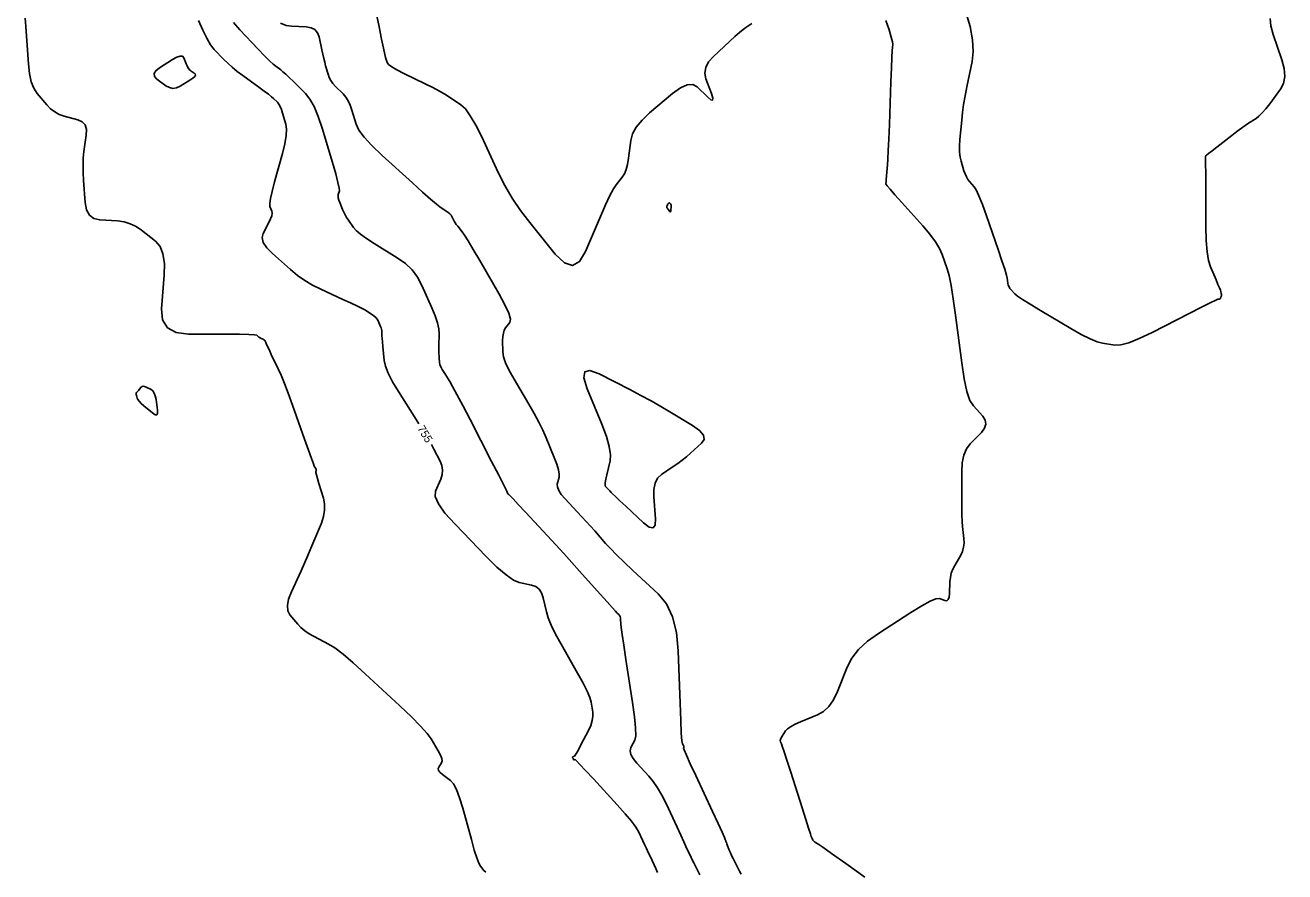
# Model space of a CAD drawing. Extents: x 2082232 to 2083549, y 592624 to 593832.
# Drawn here: x 2082685.8 to 2082796, y 593100.6 to 593174.7 of the extents above; entities that cross this region are included whole.
import ezdxf

# ---------------------------------------------------------------- set-up
doc = ezdxf.new("R2010")
doc.units = 0
doc.layers.add('DT_X_Contour_Major', color=7, linetype='Continuous')
doc.layers.add('DT_X_Contour_Minor', color=7, linetype='Continuous')

msp = doc.modelspace()

# ---------------------------------------------------------------- linework, layer by layer
at = {"layer": 'DT_X_Contour_Major'}
for points in [[(2082700.93, 593175.1), (2082701.29, 593174.24), (2082701.64, 593173.54), (2082701.98, 593172.98), (2082702.3, 593172.57), (2082703.14, 593171.69), (2082703.48, 593171.36), (2082703.87, 593171.01), (2082704.31, 593170.65), (2082704.8, 593170.28), (2082706.19, 593169.27), (2082706.66, 593168.92), (2082707.04, 593168.64), (2082707.31, 593168.42), (2082707.48, 593168.26), (2082707.82, 593167.94), (2082707.94, 593167.78), (2082708.06, 593167.57), (2082708.17, 593167.3), (2082708.28, 593166.98), (2082708.56, 593166.02), (2082708.62, 593165.6), (2082708.59, 593165.03), (2082708.47, 593164.31), (2082708.26, 593163.46), (2082707.56, 593160.98), (2082707.35, 593160.15), (2082707.21, 593159.52), (2082707.15, 593159.08), (2082707.17, 593158.83), (2082707.33, 593158.43), (2082707.36, 593158.25), (2082707.33, 593158.02), (2082707.23, 593157.75), (2082707.08, 593157.42), (2082706.58, 593156.47), (2082706.49, 593156.1), (2082706.59, 593155.68), (2082706.89, 593155.22), (2082707.38, 593154.71), (2082708.96, 593153.3), (2082709.57, 593152.8), (2082710.21, 593152.34), (2082710.89, 593151.94), (2082711.61, 593151.58), (2082713.56, 593150.7), (2082714.23, 593150.4), (2082714.77, 593150.14), (2082715.18, 593149.93), (2082715.47, 593149.77), (2082716.05, 593149.41), (2082716.25, 593149.27), (2082716.42, 593149.12), (2082716.54, 593148.97), (2082716.63, 593148.81), (2082716.82, 593148.37), (2082716.89, 593148.22), (2082716.93, 593148.09), (2082716.96, 593147.97), (2082716.96, 593147.88), (2082716.96, 593147.64), (2082716.96, 593147.51), (2082716.98, 593147.29), (2082717.01, 593146.97), (2082717.04, 593146.57), (2082717.16, 593145.36), (2082717.27, 593144.86), (2082717.52, 593144.23), (2082717.89, 593143.49), (2082718.41, 593142.64), (2082719.95, 593140.2), (2082720.2, 593139.81)], [(2082721.29, 593138.01), (2082721.52, 593137.59), (2082722.05, 593136.55), (2082722.2, 593136.16), (2082722.26, 593135.77), (2082722.23, 593135.37), (2082722.11, 593134.98), (2082721.65, 593133.93), (2082721.63, 593133.45), (2082721.91, 593132.81), (2082722.48, 593132), (2082723.36, 593131.03), (2082726.09, 593128.21), (2082727.03, 593127.28), (2082727.83, 593126.59), (2082728.47, 593126.14), (2082728.96, 593125.93), (2082730.05, 593125.7), (2082730.43, 593125.57), (2082730.72, 593125.34), (2082730.94, 593125.02), (2082731.08, 593124.6), (2082731.36, 593123.36), (2082731.51, 593122.83), (2082731.78, 593122.18), (2082732.16, 593121.42), (2082732.64, 593120.53), (2082734.09, 593118), (2082734.57, 593117.13), (2082734.93, 593116.42), (2082735.17, 593115.86), (2082735.28, 593115.45), (2082735.42, 593114.58), (2082735.43, 593114.23), (2082735.37, 593113.85), (2082735.24, 593113.43), (2082735.03, 593112.97), (2082734.37, 593111.71), (2082734.15, 593111.3), (2082733.98, 593111), (2082733.86, 593110.81), (2082733.8, 593110.73), (2082733.7, 593110.69), (2082733.67, 593110.67), (2082733.65, 593110.66), (2082733.64, 593110.64), (2082733.65, 593110.63), (2082733.67, 593110.6), (2082733.68, 593110.59), (2082733.69, 593110.57), (2082733.7, 593110.55), (2082733.7, 593110.52), (2082733.72, 593110.46), (2082733.72, 593110.44), (2082733.74, 593110.42), (2082733.76, 593110.42), (2082733.78, 593110.42), (2082733.86, 593110.43), (2082733.98, 593110.33), (2082734.29, 593110.01), (2082734.79, 593109.48), (2082735.48, 593108.74), (2082737.56, 593106.47), (2082738.26, 593105.69), (2082738.8, 593105.04), (2082739.19, 593104.52), (2082739.41, 593104.14), (2082739.8, 593103.31), (2082739.95, 593102.99), (2082740.11, 593102.65), (2082740.27, 593102.29), (2082740.45, 593101.92), (2082740.92, 593100.89), (2082741.08, 593100.55)]]:
    msp.add_lwpolyline(points, dxfattribs=at)
at = {"layer": 'DT_X_Contour_Minor'}
for points in [[(2082716.04, 593177.72), (2082716.71, 593174.54), (2082716.93, 593173.48), (2082717.11, 593172.67), (2082717.23, 593172.13), (2082717.29, 593171.85), (2082717.41, 593171.43), (2082717.53, 593171.26), (2082717.82, 593171.04), (2082718.28, 593170.77), (2082718.89, 593170.46), (2082720.75, 593169.56), (2082721.41, 593169.24), (2082721.99, 593168.93), (2082722.48, 593168.65), (2082722.89, 593168.39), (2082723.88, 593167.72), (2082724.27, 593167.36), (2082724.7, 593166.77), (2082725.18, 593165.95), (2082725.7, 593164.91), (2082727.14, 593161.81), (2082727.72, 593160.67), (2082728.37, 593159.56), (2082729.09, 593158.47), (2082729.9, 593157.42), (2082732.13, 593154.66), (2082732.93, 593153.89), (2082733.64, 593153.67), (2082734.26, 593154), (2082734.79, 593154.88), (2082736.09, 593157.94), (2082736.54, 593158.98), (2082736.92, 593159.79), (2082737.22, 593160.38), (2082737.46, 593160.73), (2082737.99, 593161.39), (2082738.18, 593161.68), (2082738.33, 593162.05), (2082738.45, 593162.5), (2082738.54, 593163.04), (2082738.74, 593164.59), (2082738.9, 593165.18), (2082739.22, 593165.78), (2082739.72, 593166.39), (2082740.38, 593167.01), (2082742.38, 593168.7), (2082743.08, 593169.21), (2082743.68, 593169.48), (2082744.17, 593169.5), (2082744.56, 593169.29), (2082745.48, 593168.39), (2082745.75, 593168.15), (2082745.9, 593168.13), (2082745.91, 593168.31), (2082745.79, 593168.7), (2082745.3, 593170), (2082745.21, 593170.5), (2082745.29, 593170.99), (2082745.54, 593171.47), (2082745.98, 593171.96), (2082747.37, 593173.26), (2082747.85, 593173.71), (2082748.25, 593174.06), (2082748.57, 593174.32), (2082748.81, 593174.49), (2082749.34, 593174.83)], [(2082726.05, 593100.59), (2082725.87, 593100.74), (2082725.58, 593101.11), (2082725.45, 593101.36), (2082725.27, 593101.83), (2082725.05, 593102.52), (2082724.79, 593103.44), (2082724.04, 593106.17), (2082723.76, 593107.09), (2082723.49, 593107.81), (2082723.22, 593108.31), (2082722.96, 593108.61), (2082722.27, 593109.12), (2082722.05, 593109.31), (2082721.93, 593109.48), (2082721.89, 593109.64), (2082721.94, 593109.78), (2082722.19, 593110.14), (2082722.24, 593110.31), (2082722.21, 593110.54), (2082722.1, 593110.83), (2082721.9, 593111.19), (2082721.27, 593112.24), (2082720.92, 593112.71), (2082720.34, 593113.35), (2082719.54, 593114.16), (2082718.52, 593115.13), (2082715.5, 593117.95), (2082714.45, 593118.9), (2082713.57, 593119.65), (2082712.85, 593120.2), (2082712.3, 593120.54), (2082711.05, 593121.19), (2082710.61, 593121.44), (2082710.22, 593121.71), (2082709.88, 593121.99), (2082709.6, 593122.29), (2082708.92, 593123.11), (2082708.74, 593123.46), (2082708.7, 593123.91), (2082708.8, 593124.46), (2082709.05, 593125.11), (2082709.89, 593126.95), (2082710.2, 593127.63), (2082710.49, 593128.29), (2082710.76, 593128.93), (2082711.02, 593129.53), (2082711.67, 593131.13), (2082711.86, 593131.71), (2082711.95, 593132.27), (2082711.95, 593132.8), (2082711.85, 593133.3), (2082711.45, 593134.59), (2082711.32, 593135.02), (2082711.23, 593135.34), (2082711.18, 593135.54), (2082711.18, 593135.63), (2082711.22, 593135.71), (2082711.22, 593135.75), (2082711.22, 593135.79), (2082711.2, 593135.85), (2082711.16, 593135.92), (2082711.05, 593136.11), (2082710.97, 593136.32), (2082710.79, 593136.78), (2082710.53, 593137.5), (2082710.18, 593138.48), (2082709.14, 593141.45), (2082708.77, 593142.48), (2082708.44, 593143.35), (2082708.15, 593144.07), (2082707.9, 593144.62), (2082707.29, 593145.89), (2082707.09, 593146.31), (2082706.94, 593146.63), (2082706.85, 593146.83), (2082706.8, 593146.93), (2082706.74, 593147.05), (2082706.72, 593147.1), (2082706.68, 593147.14), (2082706.63, 593147.17), (2082706.57, 593147.21), (2082706.39, 593147.29), (2082706.32, 593147.32), (2082706.26, 593147.36), (2082706.2, 593147.4), (2082706.15, 593147.44), (2082706.01, 593147.56), (2082705.81, 593147.6), (2082705.31, 593147.63), (2082704.5, 593147.65), (2082703.4, 593147.65), (2082700.04, 593147.65), (2082698.95, 593147.79), (2082698.2, 593148.21), (2082697.78, 593148.9), (2082697.69, 593149.87), (2082697.91, 593152.83), (2082697.93, 593153.84), (2082697.81, 593154.67), (2082697.55, 593155.32), (2082697.16, 593155.78), (2082695.93, 593156.75), (2082695.45, 593157.08), (2082694.94, 593157.32), (2082694.4, 593157.48), (2082693.84, 593157.56), (2082692.28, 593157.65), (2082691.77, 593157.78), (2082691.38, 593158.07), (2082691.13, 593158.53), (2082691.01, 593159.17), (2082690.86, 593161.09), (2082690.82, 593161.79), (2082690.82, 593162.45), (2082690.84, 593163.06), (2082690.9, 593163.63), (2082691.1, 593165.08), (2082691.11, 593165.57), (2082690.99, 593165.96), (2082690.74, 593166.23), (2082690.36, 593166.41), (2082689.17, 593166.73), (2082688.74, 593166.88), (2082688.34, 593167.1), (2082687.98, 593167.38), (2082687.64, 593167.72), (2082686.79, 593168.72), (2082686.51, 593169.17), (2082686.29, 593169.74), (2082686.13, 593170.45), (2082686.04, 593171.3), (2082685.88, 593173.73), (2082685.82, 593174.58), (2082685.76, 593175.29)], [(2082794.69, 593175.26), (2082794.73, 593174.62), (2082794.94, 593173.86), (2082795.7, 593171.67), (2082795.91, 593170.89), (2082795.96, 593170.2), (2082795.85, 593169.59), (2082795.57, 593169.08), (2082794.64, 593167.81), (2082794.3, 593167.37), (2082793.98, 593167.01), (2082793.7, 593166.73), (2082793.44, 593166.53), (2082792.77, 593166.11), (2082792.5, 593165.92), (2082792.16, 593165.68), (2082791.76, 593165.38), (2082791.31, 593165.03), (2082790.02, 593164.03), (2082789.6, 593163.69), (2082789.29, 593163.46), (2082789.11, 593163.31), (2082789.05, 593163.26), (2082789.04, 593163.26), (2082789.04, 593163.26), (2082789.04, 593163.25), (2082789.04, 593163.25), (2082789.04, 593163.25), (2082789.04, 593163.25), (2082789.04, 593163.25), (2082789.04, 593163.25), (2082789.04, 593163.25), (2082789.03, 593163.24), (2082789.03, 593163.23), (2082789.03, 593163.07), (2082789.03, 593162.57), (2082789.04, 593161.74), (2082789.04, 593160.59), (2082789.06, 593157.07), (2082789.09, 593155.86), (2082789.17, 593154.87), (2082789.29, 593154.1), (2082789.45, 593153.56), (2082789.95, 593152.4), (2082790.11, 593152.01), (2082790.24, 593151.71), (2082790.32, 593151.51), (2082790.35, 593151.39), (2082790.4, 593151.21), (2082790.41, 593151.14), (2082790.42, 593151.09), (2082790.42, 593151.04), (2082790.41, 593151), (2082790.37, 593150.9), (2082790.36, 593150.86), (2082790.34, 593150.84), (2082790.33, 593150.81), (2082790.32, 593150.8), (2082790.3, 593150.76), (2082790.29, 593150.75), (2082790.27, 593150.74), (2082790.24, 593150.73), (2082790.2, 593150.73), (2082790.1, 593150.72), (2082789.92, 593150.64), (2082789.43, 593150.41), (2082788.66, 593150.02), (2082787.59, 593149.47), (2082784.34, 593147.8), (2082783.22, 593147.27), (2082782.31, 593146.9), (2082781.6, 593146.71), (2082781.09, 593146.68), (2082780.02, 593146.86), (2082779.55, 593146.99), (2082778.92, 593147.25), (2082778.15, 593147.64), (2082777.23, 593148.16), (2082774.58, 593149.73), (2082773.69, 593150.27), (2082773.02, 593150.68), (2082772.57, 593150.99), (2082772.34, 593151.18), (2082772.02, 593151.53), (2082771.91, 593151.66), (2082771.83, 593151.8), (2082771.77, 593151.95), (2082771.73, 593152.11), (2082771.68, 593152.54), (2082771.61, 593152.81), (2082771.46, 593153.33), (2082771.21, 593154.08), (2082770.87, 593155.06), (2082769.85, 593158.01), (2082769.5, 593159), (2082769.2, 593159.75), (2082768.96, 593160.27), (2082768.78, 593160.56), (2082768.38, 593161), (2082768.24, 593161.19), (2082768.11, 593161.41), (2082767.99, 593161.67), (2082767.89, 593161.96), (2082767.63, 593162.79), (2082767.55, 593163.14), (2082767.51, 593163.58), (2082767.5, 593164.09), (2082767.54, 593164.68), (2082767.69, 593166.38), (2082767.76, 593167.04), (2082767.86, 593167.74), (2082767.99, 593168.5), (2082768.14, 593169.3), (2082768.6, 593171.5), (2082768.69, 593172.39), (2082768.63, 593173.41), (2082768.42, 593174.56), (2082768.06, 593175.83)], [(2082703.99, 593174.92), (2082704.54, 593174.29), (2082706.15, 593172.59), (2082706.69, 593172.02), (2082707.13, 593171.58), (2082707.46, 593171.27), (2082707.68, 593171.09), (2082708.11, 593170.77), (2082708.3, 593170.62), (2082708.55, 593170.4), (2082708.86, 593170.11), (2082709.23, 593169.75), (2082710.28, 593168.71), (2082710.67, 593168.23), (2082711.04, 593167.56), (2082711.4, 593166.71), (2082711.74, 593165.68), (2082712.64, 593162.67), (2082712.92, 593161.67), (2082713.12, 593160.93), (2082713.23, 593160.43), (2082713.24, 593160.19), (2082713.15, 593159.87), (2082713.14, 593159.74), (2082713.15, 593159.58), (2082713.2, 593159.39), (2082713.28, 593159.17), (2082713.52, 593158.55), (2082713.63, 593158.32), (2082713.74, 593158.09), (2082713.88, 593157.85), (2082714.03, 593157.62), (2082714.47, 593156.99), (2082714.7, 593156.73), (2082715.09, 593156.41), (2082715.62, 593156.03), (2082716.3, 593155.59), (2082718.31, 593154.34), (2082719.02, 593153.84), (2082719.61, 593153.27), (2082720.09, 593152.63), (2082720.47, 593151.92), (2082721.34, 593149.95), (2082721.62, 593149.25), (2082721.82, 593148.64), (2082721.94, 593148.12), (2082721.97, 593147.68), (2082721.95, 593146.63), (2082721.95, 593146.27), (2082721.95, 593145.97), (2082721.96, 593145.73), (2082721.97, 593145.56), (2082722, 593145.17), (2082722.04, 593145.01), (2082722.12, 593144.81), (2082722.24, 593144.57), (2082722.4, 593144.29), (2082722.9, 593143.51), (2082723.15, 593143.08), (2082723.53, 593142.39), (2082724.04, 593141.42), (2082724.68, 593140.18), (2082726.56, 593136.51), (2082727.18, 593135.31), (2082727.62, 593134.45), (2082727.88, 593133.93), (2082727.96, 593133.75), (2082727.96, 593133.74), (2082727.96, 593133.73), (2082727.96, 593133.72), (2082727.97, 593133.71), (2082727.98, 593133.7), (2082728.02, 593133.66), (2082728.03, 593133.65), (2082728.04, 593133.64), (2082728.05, 593133.63), (2082728.06, 593133.63), (2082728.07, 593133.63), (2082728.17, 593133.53), (2082728.44, 593133.24), (2082728.9, 593132.75), (2082729.53, 593132.07), (2082731.46, 593130), (2082732.18, 593129.22), (2082732.89, 593128.45), (2082733.58, 593127.69), (2082734.26, 593126.93), (2082736.06, 593124.9), (2082736.66, 593124.23), (2082737.1, 593123.73), (2082737.39, 593123.41), (2082737.53, 593123.26), (2082737.71, 593123.1), (2082737.76, 593123.03), (2082737.81, 593122.94), (2082737.83, 593122.83), (2082737.85, 593122.69), (2082737.86, 593122.3), (2082737.89, 593122), (2082737.98, 593121.38), (2082738.12, 593120.44), (2082738.31, 593119.19), (2082738.9, 593115.44), (2082739.07, 593114.18), (2082739.16, 593113.2), (2082739.17, 593112.52), (2082739.08, 593112.13), (2082738.74, 593111.48), (2082738.68, 593111.21), (2082738.74, 593110.89), (2082738.94, 593110.53), (2082739.27, 593110.13), (2082740.32, 593108.99), (2082740.71, 593108.51), (2082741.09, 593107.96), (2082741.46, 593107.31), (2082741.83, 593106.58), (2082742.79, 593104.51), (2082743.12, 593103.81), (2082743.37, 593103.25), (2082743.56, 593102.84), (2082743.68, 593102.58), (2082743.92, 593102.08), (2082744.01, 593101.88), (2082744.12, 593101.65), (2082744.25, 593101.4), (2082744.39, 593101.12), (2082744.79, 593100.35)], [(2082708.1, 593174.86), (2082708.58, 593174.66), (2082709.06, 593174.59), (2082710.34, 593174.54), (2082710.77, 593174.47), (2082711.1, 593174.3), (2082711.34, 593174.03), (2082711.47, 593173.66), (2082711.71, 593172.54), (2082711.79, 593172.14), (2082711.88, 593171.77), (2082711.96, 593171.44), (2082712.04, 593171.14), (2082712.25, 593170.39), (2082712.35, 593170.11), (2082712.49, 593169.84), (2082712.68, 593169.58), (2082712.91, 593169.33), (2082713.57, 593168.67), (2082713.81, 593168.4), (2082714.01, 593168.07), (2082714.19, 593167.69), (2082714.34, 593167.26), (2082714.71, 593166.03), (2082714.95, 593165.51), (2082715.41, 593164.89), (2082716.09, 593164.15), (2082716.98, 593163.3), (2082719.63, 593160.89), (2082720.53, 593160.08), (2082721.23, 593159.46), (2082721.73, 593159.04), (2082722.03, 593158.8), (2082722.58, 593158.43), (2082722.76, 593158.3), (2082722.91, 593158.17), (2082723.02, 593158.06), (2082723.08, 593157.95), (2082723.22, 593157.66), (2082723.28, 593157.55), (2082723.36, 593157.41), (2082723.47, 593157.26), (2082723.6, 593157.09), (2082723.99, 593156.62), (2082724.19, 593156.33), (2082724.52, 593155.81), (2082724.96, 593155.06), (2082725.53, 593154.09), (2082727.2, 593151.2), (2082727.73, 593150.23), (2082728.07, 593149.48), (2082728.21, 593148.96), (2082728.17, 593148.67), (2082727.79, 593148.2), (2082727.67, 593148), (2082727.59, 593147.75), (2082727.54, 593147.45), (2082727.52, 593147.1), (2082727.54, 593146.11), (2082727.6, 593145.68), (2082727.79, 593145.14), (2082728.1, 593144.48), (2082728.53, 593143.72), (2082729.83, 593141.52), (2082730.29, 593140.72), (2082730.7, 593139.96), (2082731.04, 593139.25), (2082731.33, 593138.59), (2082732.04, 593136.87), (2082732.26, 593136.28), (2082732.41, 593135.79), (2082732.47, 593135.41), (2082732.46, 593135.14), (2082732.31, 593134.54), (2082732.32, 593134.29), (2082732.43, 593133.99), (2082732.66, 593133.64), (2082733, 593133.24), (2082734.06, 593132.11), (2082734.45, 593131.68), (2082734.84, 593131.26), (2082735.21, 593130.85), (2082735.58, 593130.44), (2082736.54, 593129.35), (2082736.96, 593128.9), (2082737.5, 593128.35), (2082738.15, 593127.72), (2082738.92, 593126.99), (2082741.12, 593124.94), (2082741.85, 593124.05), (2082742.39, 593122.93), (2082742.73, 593121.56), (2082742.89, 593119.96), (2082743.05, 593115.36), (2082743.11, 593113.84), (2082743.16, 593112.75), (2082743.21, 593112.06), (2082743.25, 593111.8), (2082743.34, 593111.66), (2082743.37, 593111.61), (2082743.39, 593111.56), (2082743.39, 593111.53), (2082743.39, 593111.5), (2082743.35, 593111.44), (2082743.4, 593111.28), (2082743.6, 593110.82), (2082743.94, 593110.07), (2082744.42, 593109.03), (2082745.88, 593105.88), (2082746.37, 593104.84), (2082746.72, 593104.08), (2082746.93, 593103.61), (2082747.01, 593103.43), (2082747.04, 593103.32), (2082747.06, 593103.27), (2082747.1, 593103.18), (2082747.14, 593103.06), (2082747.2, 593102.9), (2082747.38, 593102.45), (2082747.46, 593102.26), (2082747.56, 593102.04), (2082747.69, 593101.78), (2082747.84, 593101.5), (2082748.26, 593100.68), (2082748.4, 593100.41)], [(2082761.05, 593175.1), (2082761.33, 593174.27), (2082761.53, 593173.65), (2082761.64, 593173.23), (2082761.67, 593173.02), (2082761.63, 593172.73), (2082761.61, 593172.46), (2082761.59, 593171.87), (2082761.55, 593170.95), (2082761.5, 593169.72), (2082761.37, 593166), (2082761.32, 593164.73), (2082761.27, 593163.72), (2082761.24, 593162.97), (2082761.2, 593162.48), (2082761.12, 593161.52), (2082761.09, 593161.2), (2082761.07, 593160.97), (2082761.06, 593160.83), (2082761.06, 593160.78), (2082761.07, 593160.75), (2082761.16, 593160.64), (2082761.42, 593160.35), (2082761.85, 593159.86), (2082762.45, 593159.18), (2082764.28, 593157.12), (2082764.91, 593156.39), (2082765.4, 593155.73), (2082765.76, 593155.14), (2082765.99, 593154.63), (2082766.42, 593153.38), (2082766.59, 593152.78), (2082766.77, 593151.9), (2082766.95, 593150.74), (2082767.15, 593149.32), (2082767.69, 593145.16), (2082767.9, 593143.75), (2082768.15, 593142.65), (2082768.41, 593141.85), (2082768.71, 593141.37), (2082769.53, 593140.48), (2082769.75, 593140.14), (2082769.8, 593139.79), (2082769.69, 593139.43), (2082769.41, 593139.06), (2082768.43, 593138.07), (2082768.11, 593137.63), (2082767.88, 593137.08), (2082767.74, 593136.4), (2082767.69, 593135.6), (2082767.69, 593133.32), (2082767.69, 593132.52), (2082767.7, 593131.84), (2082767.73, 593131.27), (2082767.77, 593130.82), (2082767.89, 593129.77), (2082767.91, 593129.38), (2082767.86, 593129.01), (2082767.76, 593128.65), (2082767.6, 593128.31), (2082767.08, 593127.42), (2082766.91, 593127.08), (2082766.78, 593126.73), (2082766.7, 593126.37), (2082766.66, 593125.99), (2082766.62, 593124.97), (2082766.58, 593124.65), (2082766.51, 593124.43), (2082766.39, 593124.33), (2082766.22, 593124.34), (2082765.74, 593124.52), (2082765.44, 593124.49), (2082764.93, 593124.28), (2082764.2, 593123.88), (2082763.25, 593123.29), (2082760.42, 593121.47), (2082759.45, 593120.78), (2082758.67, 593120.06), (2082758.08, 593119.3), (2082757.66, 593118.52), (2082756.82, 593116.4), (2082756.47, 593115.67), (2082756.06, 593115.09), (2082755.6, 593114.65), (2082755.08, 593114.35), (2082753.6, 593113.74), (2082753.11, 593113.52), (2082752.72, 593113.31), (2082752.45, 593113.12), (2082752.28, 593112.94), (2082751.98, 593112.49), (2082751.89, 593112.33), (2082751.83, 593112.2), (2082751.81, 593112.09), (2082751.83, 593112), (2082751.91, 593111.81), (2082751.99, 593111.61), (2082752.15, 593111.12), (2082752.4, 593110.37), (2082752.73, 593109.34), (2082753.72, 593106.22), (2082754.05, 593105.19), (2082754.3, 593104.43), (2082754.46, 593103.94), (2082754.53, 593103.71), (2082754.63, 593103.48), (2082754.67, 593103.39), (2082754.73, 593103.31), (2082754.81, 593103.24), (2082754.91, 593103.17), (2082755.19, 593102.99), (2082755.53, 593102.77), (2082756.31, 593102.22), (2082757.54, 593101.35), (2082759.22, 593100.15)], [(2082699.31, 593169.35), (2082698.99, 593169.2), (2082698.68, 593169.16), (2082698.37, 593169.23), (2082698.07, 593169.39), (2082697.27, 593169.98), (2082697.06, 593170.21), (2082697.03, 593170.45), (2082697.18, 593170.7), (2082697.51, 593170.96), (2082698.64, 593171.68), (2082699.02, 593171.89), (2082699.31, 593171.99), (2082699.52, 593171.97), (2082699.64, 593171.83), (2082699.85, 593171.31), (2082699.92, 593171.13), (2082699.98, 593171), (2082700.03, 593170.91), (2082700.06, 593170.86), (2082700.12, 593170.79), (2082700.16, 593170.76), (2082700.21, 593170.72), (2082700.28, 593170.66), (2082700.36, 593170.6), (2082700.62, 593170.42), (2082700.66, 593170.33), (2082700.6, 593170.21), (2082700.43, 593170.06), (2082700.16, 593169.88), (2082699.31, 593169.35)], [(2082742.12, 593158.41), (2082742.17, 593158.35), (2082742.21, 593158.35), (2082742.23, 593158.39), (2082742.25, 593158.49), (2082742.26, 593158.79), (2082742.27, 593158.9), (2082742.26, 593158.98), (2082742.25, 593159.03), (2082742.22, 593159.07), (2082742.15, 593159.13), (2082742.12, 593159.15), (2082742.1, 593159.15), (2082742.08, 593159.15), (2082742.06, 593159.13), (2082742.01, 593159.07), (2082741.99, 593159.05), (2082741.97, 593159.02), (2082741.96, 593158.98), (2082741.94, 593158.95), (2082741.89, 593158.84), (2082741.89, 593158.79), (2082741.9, 593158.74), (2082741.92, 593158.68), (2082741.97, 593158.61), (2082742.12, 593158.41)], [(2082736.9, 593133.95), (2082736.85, 593134.01), (2082736.79, 593134.06), (2082736.74, 593134.12), (2082736.68, 593134.18), (2082736.54, 593134.34), (2082736.5, 593134.45), (2082736.51, 593134.66), (2082736.55, 593134.96), (2082736.64, 593135.36), (2082736.93, 593136.56), (2082736.97, 593137.1), (2082736.86, 593137.82), (2082736.6, 593138.71), (2082736.2, 593139.78), (2082734.93, 593142.88), (2082734.64, 593143.83), (2082734.71, 593144.37), (2082735.16, 593144.48), (2082735.98, 593144.18), (2082738.65, 593142.81), (2082739.62, 593142.3), (2082740.53, 593141.81), (2082741.37, 593141.33), (2082742.15, 593140.87), (2082744.15, 593139.66), (2082744.76, 593139.23), (2082745.09, 593138.82), (2082745.15, 593138.45), (2082744.93, 593138.11), (2082743.96, 593137.25), (2082743.6, 593136.93), (2082743.23, 593136.63), (2082742.85, 593136.34), (2082742.46, 593136.07), (2082741.42, 593135.37), (2082741.08, 593135.05), (2082740.86, 593134.62), (2082740.75, 593134.07), (2082740.75, 593133.41), (2082740.9, 593131.5), (2082740.88, 593130.94), (2082740.69, 593130.7), (2082740.35, 593130.77), (2082739.85, 593131.15), (2082738.3, 593132.6), (2082737.78, 593133.08), (2082737.4, 593133.44), (2082737.15, 593133.68), (2082737.03, 593133.8), (2082736.9, 593133.95)], [(2082695.54, 593142.6), (2082695.57, 593142.63), (2082695.62, 593142.67), (2082695.67, 593142.73), (2082695.73, 593142.81), (2082695.9, 593143.02), (2082695.98, 593143.08), (2082696.08, 593143.1), (2082696.2, 593143.08), (2082696.35, 593143.02), (2082696.78, 593142.8), (2082696.92, 593142.69), (2082697.04, 593142.5), (2082697.13, 593142.25), (2082697.2, 593141.94), (2082697.33, 593141), (2082697.34, 593140.72), (2082697.27, 593140.59), (2082697.12, 593140.6), (2082696.88, 593140.76), (2082696.14, 593141.39), (2082695.9, 593141.6), (2082695.72, 593141.79), (2082695.6, 593141.93), (2082695.54, 593142.05), (2082695.48, 593142.3), (2082695.46, 593142.38), (2082695.45, 593142.45), (2082695.46, 593142.5), (2082695.48, 593142.54), (2082695.54, 593142.6)]]:
    msp.add_lwpolyline(points, dxfattribs=at)

# ---------------------------------------------------------------- texts
at = {"layer": 'DT_X_Contour_Major'}
msp.add_text('755', height=0.7, rotation=301.1693, dxfattribs=at).set_placement((2082720.04, 593139.41))

doc.saveas('drawing.dxf')
